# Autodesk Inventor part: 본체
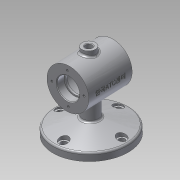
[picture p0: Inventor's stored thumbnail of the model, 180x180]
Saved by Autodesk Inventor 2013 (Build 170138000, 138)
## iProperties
Created: 2018-12
Part Number: 본체
Material: 알루미늄 6061
Document SubType Name: Modeling
Designer: Administrator
Density: 2.71 g/cm^3
Mass: 687.649 g
Surface Area: 555.499 cm^2
Volume: 253.745 cm^3
Author: Administrator
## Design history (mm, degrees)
sketch "스케치2"
  geometry: C1 r 30 at (0, 0); 1 further point
  constraints: 1 centre point, 1 coincident
  dimensions: "d3" = 60 diameter of C1
extrude "돌출1" new body sketch "스케치2" stored distance "d5" = 70; taper "d6" = 0 deg
sketch "스케치3"
  geometry: C1 r 30 at (0, 0) reference; 1 further point
  constraints: 1 coincident
hole "구멍1" sketch "스케치3" at (0, 0) diameter "d7" = 28; stored, may be unused: countersink angle "d11" = 90 deg, drill point angle "d13" = 0 deg; dims "d8" = 6, "d9" = 32, "d10" = 12, "d12" = 15
sketch "스케치5"
  geometry: C1 r 14 at (0, 0) reference; C2 r 25 at (0, 0)
  constraints: 1 centre point, 1 coincident
  dimensions: "d18" = 50 diameter of C2
extrude "돌출3" cut sketch "스케치5" distance "d20" = 40; taper "d21" = 0 deg
sketch "스케치6" dims "d22" = 46
  geometry: C1 r 16 at (0, 0) reference; C2 r 30 at (0, 0) reference; 2 further points
  constraints: 1 coincident, 1 vertical alignment, 2 other
  dimensions: "d25" = 23 distance of point (0, 23) C1.centre
hole "구멍2" sketch "스케치6" at (0, 23) diameter "d26" = 3.242; stored, may be unused: countersink angle "d30" = 90 deg, drill point angle "d32" = 118 deg; dims "d27" = 8, "d28" = 32, "d29" = 12, "d31" = 10
node "작업 평면1"
sketch "스케치7"
  geometry: C1 r 10 at (0, 0); 1 further point
  constraints: 1 centre point, 1 coincident
  dimensions: "d37" = 20 diameter of C1
extrude "돌출4" join sketch "스케치7" stored distance "d39" = 40; taper "d40" = 0 deg
sketch "스케치9"
  geometry: C1 r 10 at (0, 0) reference; C2 r 5 at (0, 0)
  constraints: 1 centre point, 1 coincident
  dimensions: "d41" = 10 diameter of C2
extrude "돌출5" cut sketch "스케치9" distance "d43" = 40; taper "d44" = 0 deg
node "작업 평면2"
sketch "스케치10"
  geometry: C1 r 55 at (0, 0); 1 further point
  constraints: 1 centre point, 1 coincident
  dimensions: "d46" = 110 diameter of C1
extrude "돌출6" join sketch "스케치10" distance "d48" = 11; taper "d49" = 0 deg
sketch "스케치15"
  geometry: C1 r 55 at (0, 0) reference; A1 r 44 centre (0, 0) between (0, 44) and (44, 0); 2 further points
  constraints: 4 point on circle, 1 centre point, 1 coincident
  dimensions: "d69" = 88 diameter of A1
extrude "돌출8" join sketch "스케치15" distance "d54" = 15; taper "d55" = -75 deg
sketch "스케치16"
  geometry: C1 r 55 at (0, 0) reference; C2 r 12 at (0, 0)
  constraints: 1 centre point, 1 coincident
  dimensions: "d56" = 24 diameter of C2
extrude "돌출9" join sketch "스케치16" stored distance "d58" = 15; taper "d59" = 0 deg
sketch "스케치17"
  geometry: C1 r 55 at (0, 0) reference; A1 r 44 centre (0, 0) between (0, 44) and (44, 0); 2 further points
  constraints: 4 point on circle, 1 centre point, 1 coincident
  dimensions: "d60" = 88 diameter of A1
hole "구멍3" sketch "스케치17" at (0, 44), (44, 0), (0, -44), (-44, 0) diameter "d62" = 9; stored, may be unused: countersink angle "d66" = 90 deg, drill point angle "d68" = 118 deg; dims "d63" = 8, "d64" = 32, "d65" = 12, "d67" = 10
node "작업 평면4"
sketch "스케치18" dims "d73" = 88
  geometry: C1 r 7 at (0, 44); 2 further points
  constraints: 1 centre point, 1 coincident, 1 vertical alignment, 2 other
  dimensions: "d75" = 14 diameter of C1
extrude "돌출10" cut sketch "스케치18" distance "d76" = 15; taper "d77" = 0 deg
chamfer "모따기1" distance "d81" = 1; stored, may be unused: second distance "d82" = 2, angle "d83" = 45 deg
fillet "모깎기1" dims "d84" = 0.3
fillet "모깎기2" dims "d85" = 3
fillet "모깎기3" dims "d86" = 3
fillet "모깎기4" dims "d87" = 3
fillet "모깎기5" dims "d88" = 3
fillet "모깎기6" dims "d89" = 1
node "작업 평면5"
sketch "스케치20"
  geometry: L1 (30, 35)-(-30, 35) reference; L2 (30, -35)-(30, 35) reference; 2 further points
  constraints: 1 other
  dimensions: "d93" = 35 distance from line of L1 point (0, 0); "d94" = 30 distance from line of L2 point (0, 0)
feature "엠보싱1" sketch "스케치20" dims "d95" = 0.5, "d96" = 0
node "솔리드1"
mirror "대칭1"
pattern_circular "원형 패턴1" dims angle "d34" = 360 deg
mirror "대칭2"
pattern_circular "원형 패턴2" dims angle "d79" = 360 deg
other parameters: "d36" = 37, "d45" = -75, "d72" = -65
